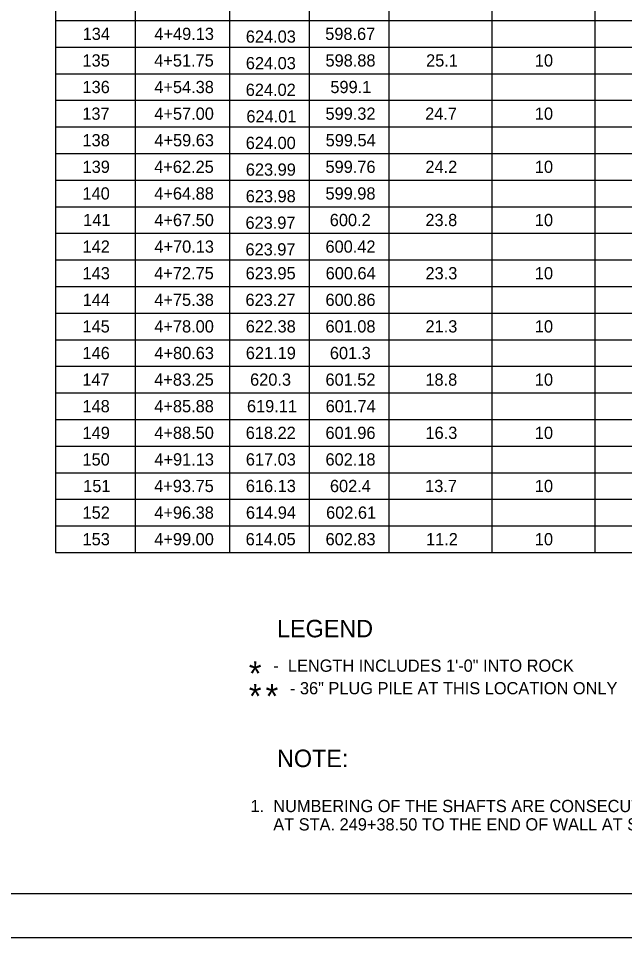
# Model space of a CAD drawing. Extents: x 0 to 34, y 0 to 22.
# Drawn here: x 21.68 to 28.62, y 0 to 10.52 of the extents above; entities that cross this region are included whole.
import ezdxf

# ---------------------------------------------------------------- set-up
doc = ezdxf.new("R2010")
doc.units = 0
for name, color, linetype in [('BR_P_Gen_Text', 7, 'Continuous'), ('SH_Border', 7, 'Continuous'), ('SH_Cut_Line', 7, 'Continuous')]:
    doc.layers.add(name, color=color, linetype=linetype)

msp = doc.modelspace()

# ---------------------------------------------------------------- linework, layer by layer
at = {"layer": 'BR_P_Gen_Text'}
for p, q in [((22.105, 21.12), (22.105, 4.407)), ((23.018, 20.702), (23.018, 4.407)), ((24.096, 20.702), (24.096, 4.407)), ((25.009, 20.702), (25.009, 4.407)), ((25.922, 20.702), (25.922, 4.407)), ((27.102, 20.702), (27.102, 4.407)), ((28.281, 20.702), (28.281, 4.407)), ((22.105, 10.494), (30.335, 10.494)), ((22.105, 10.189), (30.335, 10.189)), ((22.105, 9.885), (30.335, 9.885)), ((22.105, 9.581), (30.335, 9.581)), ((22.105, 9.276), (30.335, 9.276)), ((22.105, 8.972), (30.335, 8.972)), ((22.105, 8.668), (30.335, 8.668)), ((22.105, 8.363), (30.335, 8.363)), ((22.105, 8.059), (30.335, 8.059)), ((22.105, 7.754), (30.335, 7.754)), ((22.105, 7.45), (30.335, 7.45)), ((22.105, 7.146), (30.335, 7.146)), ((22.105, 6.841), (30.335, 6.841)), ((22.105, 6.537), (30.335, 6.537)), ((22.105, 6.233), (30.335, 6.233)), ((22.105, 5.928), (30.335, 5.928)), ((22.105, 5.624), (30.335, 5.624)), ((22.105, 5.32), (30.335, 5.32)), ((22.105, 5.015), (30.335, 5.015)), ((22.105, 4.711), (30.335, 4.711)), ((22.105, 4.407), (30.335, 4.407))]:
    msp.add_line(p, q, dxfattribs=at)
at = {"layer": 'SH_Border'}
msp.add_lwpolyline([(1.5, 21.5), (33.5, 21.5), (33.5, 0.5), (1.5, 0.5)], close=True, dxfattribs=at)
at = {"layer": 'SH_Cut_Line'}
msp.add_lwpolyline([(0, 0), (34, 0), (34, 22), (0, 22)], close=True, dxfattribs=at)

# ---------------------------------------------------------------- texts
at = {"layer": 'BR_P_Gen_Text'}
for s, height, p in [('134', 0.14, (22.416, 10.271)), ('4+49.13', 0.14, (23.237, 10.271)), ('598.67', 0.14, (25.193, 10.271)), ('624.03', 0.14, (24.284, 10.24)), ('135', 0.14, (22.414, 9.967)), ('4+51.75', 0.14, (23.235, 9.967)), ('598.88', 0.14, (25.196, 9.967)), ('25.1', 0.14, (26.348, 9.967)), ('10', 0.14, (27.593, 9.967)), ('624.03', 0.14, (24.284, 9.936)), ('136', 0.14, (22.414, 9.663)), ('4+54.38', 0.14, (23.236, 9.663)), ('599.1', 0.14, (25.252, 9.663)), ('624.02', 0.14, (24.283, 9.631)), ('137', 0.14, (22.412, 9.358)), ('4+57.00', 0.14, (23.236, 9.358)), ('624.01', 0.14, (24.29, 9.327)), ('599.32', 0.14, (25.196, 9.358)), ('24.7', 0.14, (26.337, 9.358)), ('10', 0.14, (27.593, 9.358)), ('138', 0.14, (22.414, 9.054)), ('4+59.63', 0.14, (23.237, 9.054)), ('624.00', 0.14, (24.283, 9.023)), ('599.54', 0.14, (25.198, 9.054)), ('139', 0.14, (22.415, 8.75)), ('4+62.25', 0.14, (23.235, 8.75)), ('623.99', 0.14, (24.284, 8.718)), ('599.76', 0.14, (25.196, 8.75)), ('24.2', 0.14, (26.34, 8.75)), ('10', 0.14, (27.593, 8.75)), ('140', 0.14, (22.414, 8.445)), ('4+64.88', 0.14, (23.236, 8.445)), ('623.98', 0.14, (24.283, 8.414)), ('599.98', 0.14, (25.196, 8.445)), ('141', 0.14, (22.422, 8.141)), ('4+67.50', 0.14, (23.236, 8.141)), ('623.97', 0.14, (24.28, 8.11)), ('600.2', 0.14, (25.245, 8.141)), ('23.8', 0.14, (26.34, 8.141)), ('10', 0.14, (27.593, 8.141)), ('142', 0.14, (22.415, 7.837)), ('4+70.13', 0.14, (23.237, 7.837)), ('623.97', 0.14, (24.28, 7.805)), ('600.42', 0.14, (25.196, 7.837)), ('143', 0.14, (22.415, 7.532)), ('4+72.75', 0.14, (23.235, 7.532)), ('623.95', 0.14, (24.282, 7.532)), ('600.64', 0.14, (25.198, 7.532)), ('23.3', 0.14, (26.341, 7.532)), ('10', 0.14, (27.593, 7.532)), ('144', 0.14, (22.416, 7.228)), ('4+75.38', 0.14, (23.236, 7.228)), ('623.27', 0.14, (24.28, 7.228)), ('600.86', 0.14, (25.196, 7.228)), ('145', 0.14, (22.414, 6.924)), ('4+78.00', 0.14, (23.236, 6.924)), ('622.38', 0.14, (24.283, 6.924)), ('601.08', 0.14, (25.196, 6.924)), ('21.3', 0.14, (26.341, 6.924)), ('10', 0.14, (27.593, 6.924)), ('146', 0.14, (22.414, 6.619)), ('4+80.63', 0.14, (23.237, 6.619)), ('621.19', 0.14, (24.284, 6.619)), ('601.3', 0.14, (25.246, 6.619)), ('147', 0.14, (22.412, 6.315)), ('4+83.25', 0.14, (23.235, 6.315)), ('620.3', 0.14, (24.333, 6.315)), ('601.52', 0.14, (25.196, 6.315)), ('18.8', 0.14, (26.34, 6.315)), ('10', 0.14, (27.593, 6.315)), ('148', 0.14, (22.414, 6.011)), ('4+85.88', 0.14, (23.236, 6.011)), ('619.11', 0.14, (24.297, 6.011)), ('601.74', 0.14, (25.198, 6.011)), ('149', 0.14, (22.415, 5.706)), ('4+88.50', 0.14, (23.236, 5.706)), ('618.22', 0.14, (24.283, 5.706)), ('601.96', 0.14, (25.196, 5.706)), ('16.3', 0.14, (26.341, 5.706)), ('10', 0.14, (27.593, 5.706)), ('150', 0.14, (22.414, 5.402)), ('4+91.13', 0.14, (23.237, 5.402)), ('617.03', 0.14, (24.284, 5.402)), ('602.18', 0.14, (25.196, 5.402)), ('151', 0.14, (22.422, 5.098)), ('4+93.75', 0.14, (23.235, 5.098)), ('616.13', 0.14, (24.284, 5.098)), ('602.4', 0.14, (25.247, 5.098)), ('13.7', 0.14, (26.337, 5.098)), ('10', 0.14, (27.593, 5.098)), ('152', 0.14, (22.415, 4.793)), ('4+96.38', 0.14, (23.236, 4.793)), ('614.94', 0.14, (24.285, 4.793)), ('602.61', 0.14, (25.203, 4.793)), ('153', 0.14, (22.415, 4.489)), ('4+99.00', 0.14, (23.236, 4.489)), ('614.05', 0.14, (24.282, 4.489)), ('602.83', 0.14, (25.197, 4.489)), ('11.2', 0.14, (26.347, 4.489)), ('10', 0.14, (27.593, 4.489)), ('LEGEND', 0.2, (24.641, 3.436)), ('*', 0.28, (24.318, 2.882)), ('-  LENGTH INCLUDES 1\'-0" INTO ROCK', 0.14, (24.599, 3.042)), ('*', 0.28, (24.318, 2.623)), ('*', 0.28, (24.51, 2.623)), ('- 36" PLUG PILE AT THIS LOCATION ONLY', 0.14, (24.789, 2.784)), ('NOTE:', 0.2, (24.641, 1.951)), ('1.  NUMBERING OF THE SHAFTS ARE CONSECUTIVE, SHAFTS START', 0.14, (24.338, 1.436)), ('     AT STA. 249+38.50 TO THE END OF WALL AT STA. 253+27.71.', 0.14, (24.338, 1.226))]:
    msp.add_text(s, height=height, dxfattribs=at).set_placement(p)

doc.saveas('drawing.dxf')
